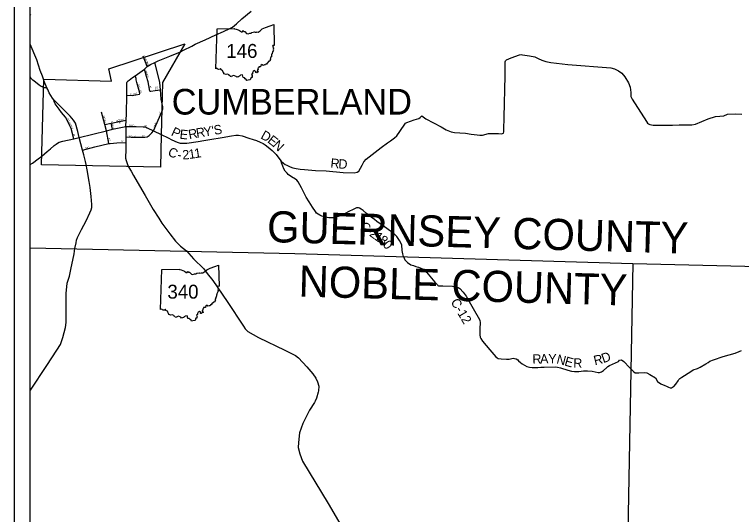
# Model space of a CAD drawing. Extents: x -452339 to 6403467, y -1 to 1814750.
# Drawn here: x -91226 to -67891, y 1614709 to 1630757 of the extents above; entities that cross this region are included whole.
import ezdxf

# ---------------------------------------------------------------- set-up
doc = ezdxf.new("R2010")
doc.units = 0
for name, color, linetype in [('Default', 7, 'Continuous'), ('GM_X_Adjacent_County_Text', 7, 'Continuous'), ('GM_X_County', 7, 'Continuous'), ('GM_X_County_Road', 7, 'Continuous'), ('GM_X_County_ROW', 7, 'Continuous'), ('GM_X_Minor_Lake', 7, 'Continuous'), ('GM_X_Minor_River', 7, 'Continuous'), ('GM_X_Minor_River_Text', 7, 'Continuous'), ('GM_X_Section_Text', 7, 'Continuous'), ('GM_X_Township_Road', 7, 'Continuous')]:
    doc.layers.add(name, color=color, linetype=linetype)

msp = doc.modelspace()

# ---------------------------------------------------------------- linework, layer by layer
at = {"layer": 'Default'}
for p, q in [((-90726, 1597935), (-90726, 1655312)), ((-84767, 1629012), (-84726, 1630303)), ((-86540, 1621284), (-86498, 1622575))]:
    msp.add_line(p, q, dxfattribs=at)
msp.add_lwpolyline([(-91226, 1655812), (-32848, 1655812), (-32848, 1597435), (-91226, 1597435)], close=True, dxfattribs=at)
for points in [[(-84726, 1630303), (-84154, 1630311), (-84162, 1630295), (-84109, 1630292), (-84051, 1630265), (-84003, 1630247), (-83943, 1630206), (-83908, 1630207), (-83893, 1630241), (-83866, 1630214), (-83833, 1630210), (-83777, 1630148), (-83731, 1630135), (-83676, 1630156), (-83635, 1630159), (-83605, 1630180), (-83526, 1630198), (-83504, 1630187), (-83463, 1630190), (-83441, 1630198), (-83405, 1630190), (-83342, 1630238), (-83276, 1630293), (-83175, 1630345), (-83024, 1630394), (-82904, 1630439), (-82887, 1629768)], [(-82887, 1629768), (-82905, 1629759), (-82932, 1629764), (-82950, 1629745), (-82928, 1629714), (-82917, 1629680), (-82927, 1629644), (-82917, 1629614), (-82923, 1629589), (-82941, 1629563), (-82947, 1629540), (-82961, 1629514), (-82960, 1629500), (-82974, 1629489), (-82972, 1629447), (-82979, 1629424), (-82976, 1629404), (-82999, 1629399), (-82994, 1629382), (-83008, 1629369), (-83005, 1629347), (-83022, 1629333), (-83006, 1629305), (-83018, 1629296), (-83029, 1629262), (-83058, 1629255), (-83116, 1629193), (-83137, 1629169), (-83160, 1629163), (-83173, 1629139), (-83201, 1629139), (-83244, 1629122), (-83272, 1629151), (-83320, 1629116), (-83326, 1629076), (-83387, 1629077), (-83385, 1629057), (-83399, 1629051), (-83411, 1629031), (-83404, 1628994), (-83433, 1628985), (-83430, 1628964), (-83411, 1628951), (-83403, 1628911), (-83433, 1628919), (-83458, 1628885), (-83484, 1628893), (-83476, 1628922), (-83520, 1628957), (-83561, 1628929), (-83582, 1628885), (-83583, 1628855), (-83614, 1628837), (-83594, 1628795), (-83597, 1628766), (-83597, 1628738), (-83635, 1628739), (-83659, 1628665)], [(-82665, 1626046), (-82595, 1625989), (-82540, 1625945), (-82481, 1625918), (-82373, 1625870), (-82290, 1625841), (-82190, 1625816), (-82061, 1625797), (-81920, 1625779), (-81565, 1625752), (-81221, 1625739), (-80679, 1625687), (-80322, 1625678), (-80224, 1625693), (-80172, 1625730), (-80072, 1625919), (-80010, 1626029), (-79937, 1626112), (-79742, 1626263), (-79452, 1626484), (-79258, 1626638), (-79154, 1626706), (-79027, 1626797), (-78956, 1626860), (-78855, 1626997), (-78680, 1627269), (-78632, 1627292), (-78393, 1627377), (-78253, 1627424), (-78204, 1627453), (-78156, 1627504), (-78018, 1627410), (-77533, 1627149), (-77370, 1627060), (-77205, 1626991), (-77104, 1626969), (-76934, 1626958), (-76754, 1626949), (-76573, 1626919), (-76372, 1626891), (-76293, 1626880), (-76203, 1626882), (-76016, 1626933), (-75924, 1626937), (-75690, 1626933), (-75604, 1626929), (-75566, 1626939), (-75534, 1626954), (-75523, 1626996), (-75516, 1627060), (-75508, 1627467), (-75480, 1628789), (-75473, 1629177), (-75471, 1629241), (-75463, 1629272), (-75432, 1629302), (-75285, 1629365), (-75011, 1629462), (-74967, 1629471), (-74919, 1629468), (-74690, 1629436), (-74526, 1629395), (-74415, 1629347), (-74300, 1629293), (-74167, 1629248), (-74006, 1629212), (-73469, 1629156), (-72086, 1629042), (-71971, 1629016), (-71834, 1628948), (-71733, 1628872), (-71632, 1628752), (-71519, 1628560), (-71468, 1628421), (-71447, 1628253), (-71443, 1628129), (-71397, 1628040), (-70938, 1627322), (-70903, 1627268), (-70873, 1627251), (-70830, 1627231), (-70724, 1627209), (-70358, 1627202), (-70102, 1627208), (-69894, 1627213), (-69486, 1627218), (-69371, 1627243), (-68960, 1627414), (-68726, 1627489), (-68582, 1627497), (-68462, 1627510), (-68335, 1627558), (-68067, 1627567), (-67879, 1627558)], [(-83659, 1628665), (-83725, 1628651), (-83771, 1628643), (-83788, 1628676), (-83821, 1628694), (-83843, 1628728), (-83890, 1628732), (-83902, 1628779), (-83907, 1628817), (-83972, 1628808), (-83990, 1628784), (-84013, 1628778), (-84026, 1628755), (-84058, 1628753), (-84092, 1628742), (-84114, 1628765), (-84169, 1628788), (-84194, 1628800), (-84246, 1628781), (-84257, 1628759), (-84298, 1628769), (-84308, 1628793), (-84333, 1628801), (-84339, 1628826), (-84392, 1628840), (-84433, 1628835), (-84506, 1628855), (-84510, 1628889), (-84535, 1628930), (-84547, 1628959), (-84593, 1628981), (-84602, 1629015), (-84617, 1629014), (-84630, 1629000), (-84681, 1628994), (-84701, 1629007), (-84730, 1629031), (-84767, 1629012)], [(-86518, 1626906), (-86298, 1626795), (-86180, 1626740), (-86005, 1626661), (-85968, 1626645), (-85909, 1626628), (-85855, 1626623), (-85782, 1626623), (-85690, 1626633), (-85329, 1626685), (-85151, 1626716), (-84955, 1626747), (-84558, 1626811), (-84264, 1626865), (-84120, 1626881), (-84039, 1626881), (-83920, 1626858), (-83706, 1626790), (-83570, 1626747), (-83454, 1626710), (-83340, 1626663), (-83247, 1626620), (-83179, 1626571), (-83083, 1626498), (-82958, 1626394), (-82830, 1626260), (-82738, 1626147), (-82665, 1626046)], [(-78742, 1622988), (-78761, 1623078), (-78784, 1623179), (-78798, 1623360), (-78868, 1623504), (-78954, 1623630), (-79048, 1623725), (-79120, 1623783), (-79230, 1623857), (-79392, 1623970), (-79594, 1624116), (-79671, 1624181), (-79781, 1624255), (-79929, 1624372), (-80038, 1624465), (-80099, 1624511), (-80150, 1624542), (-80188, 1624557), (-80217, 1624557), (-80249, 1624549), (-80309, 1624525), (-80377, 1624490), (-80473, 1624442), (-80637, 1624360), (-80802, 1624285), (-80907, 1624247), (-80969, 1624231), (-81040, 1624226), (-81137, 1624231), (-81239, 1624253), (-81358, 1624286), (-81430, 1624313), (-81484, 1624347), (-81528, 1624385), (-81569, 1624439), (-81666, 1624577), (-81768, 1624741), (-81862, 1624896), (-82016, 1625191), (-82122, 1625382), (-82166, 1625436), (-82208, 1625472), (-82330, 1625546), (-82438, 1625627), (-82479, 1625665), (-82535, 1625734), (-82581, 1625809), (-82615, 1625893), (-82655, 1625992), (-82665, 1626046)], [(-78742, 1622988), (-78696, 1622886), (-78613, 1622802), (-78507, 1622726), (-78418, 1622697), (-78343, 1622669), (-78263, 1622651), (-78150, 1622606), (-78089, 1622560), (-78006, 1622483), (-77733, 1622165), (-77653, 1622077), (-77639, 1622064), (-77613, 1622051), (-77587, 1622052), (-77473, 1622046), (-77172, 1622035), (-77042, 1622015), (-76984, 1621994), (-76933, 1621959), (-76827, 1621849), (-76733, 1621716), (-76636, 1621548), (-76500, 1621320), (-76302, 1620971), (-76285, 1620931), (-76282, 1620871), (-76291, 1620667), (-76293, 1620538), (-76290, 1620470), (-76278, 1620400), (-76256, 1620353), (-76206, 1620276), (-75969, 1619995), (-75771, 1619766), (-75737, 1619735), (-75697, 1619718), (-75606, 1619709), (-75436, 1619690), (-75352, 1619696), (-75221, 1619724), (-75173, 1619717), (-75120, 1619704), (-75074, 1619677), (-75043, 1619645), (-74986, 1619584), (-74932, 1619545), (-74778, 1619460), (-74696, 1619435), (-74610, 1619425), (-74432, 1619430), (-74332, 1619440), (-74228, 1619441), (-73864, 1619450), (-73798, 1619439), (-73703, 1619411), (-73468, 1619337), (-73346, 1619307), (-73255, 1619294), (-73111, 1619293), (-72958, 1619316), (-72888, 1619321), (-72830, 1619324), (-72682, 1619307), (-72493, 1619268), (-72445, 1619267), (-72381, 1619284), (-72318, 1619335), (-72216, 1619425), (-72176, 1619462), (-72125, 1619491), (-71841, 1619618), (-71839, 1619620)], [(-86498, 1622575), (-85926, 1622583), (-85935, 1622567), (-85881, 1622564), (-85823, 1622537), (-85775, 1622519), (-85716, 1622478), (-85680, 1622479), (-85665, 1622512), (-85638, 1622486), (-85605, 1622482), (-85550, 1622420), (-85503, 1622407), (-85448, 1622428), (-85407, 1622431), (-85377, 1622452), (-85299, 1622470), (-85276, 1622459), (-85235, 1622462), (-85214, 1622469), (-85177, 1622462), (-85114, 1622509), (-85048, 1622565), (-84947, 1622617), (-84796, 1622666), (-84677, 1622711), (-84659, 1622040)], [(-84659, 1622040), (-84677, 1622031), (-84704, 1622035), (-84723, 1622017), (-84700, 1621985), (-84689, 1621952), (-84699, 1621916), (-84689, 1621886), (-84696, 1621860), (-84713, 1621835), (-84719, 1621811), (-84734, 1621786), (-84733, 1621772), (-84746, 1621761), (-84744, 1621719), (-84751, 1621696), (-84748, 1621676), (-84771, 1621671), (-84766, 1621654), (-84780, 1621641), (-84777, 1621619), (-84794, 1621605), (-84778, 1621577), (-84791, 1621568), (-84801, 1621534), (-84830, 1621527), (-84888, 1621465), (-84909, 1621441), (-84932, 1621435), (-84945, 1621411), (-84973, 1621411), (-85016, 1621394), (-85044, 1621423), (-85093, 1621388), (-85098, 1621348), (-85160, 1621349), (-85157, 1621329), (-85171, 1621323), (-85183, 1621302), (-85176, 1621266), (-85205, 1621257), (-85202, 1621236), (-85183, 1621223), (-85175, 1621183), (-85206, 1621191), (-85231, 1621157), (-85257, 1621165), (-85248, 1621194), (-85292, 1621228), (-85333, 1621201), (-85355, 1621156), (-85355, 1621126), (-85386, 1621109), (-85366, 1621067), (-85370, 1621038), (-85369, 1621010), (-85407, 1621011), (-85431, 1620937)], [(-85431, 1620937), (-85497, 1620923), (-85544, 1620915), (-85560, 1620948), (-85593, 1620966), (-85615, 1621000), (-85663, 1621004), (-85674, 1621051), (-85679, 1621089), (-85744, 1621079), (-85762, 1621056), (-85785, 1621050), (-85798, 1621027), (-85830, 1621025), (-85864, 1621014), (-85886, 1621037), (-85941, 1621060), (-85966, 1621071), (-86018, 1621053), (-86029, 1621031), (-86070, 1621041), (-86080, 1621065), (-86105, 1621073), (-86111, 1621098), (-86164, 1621112), (-86206, 1621106), (-86278, 1621127), (-86282, 1621161), (-86307, 1621202), (-86319, 1621231), (-86365, 1621252), (-86375, 1621287), (-86389, 1621286), (-86402, 1621272), (-86453, 1621265), (-86474, 1621279), (-86502, 1621303), (-86540, 1621284)], [(-71839, 1619620), (-71809, 1619662), (-71738, 1619671), (-71665, 1619619), (-71482, 1619423), (-71362, 1619296), (-71299, 1619253), (-71187, 1619253), (-71002, 1619271), (-70927, 1619253), (-70832, 1619199), (-70653, 1619092), (-70582, 1618972), (-70483, 1618903), (-70356, 1618845), (-70301, 1618824), (-70235, 1618791), (-70180, 1618774), (-70142, 1618773), (-70101, 1618790), (-70061, 1618815), (-69996, 1618896), (-69926, 1618995), (-69897, 1619038), (-69871, 1619070), (-69808, 1619116), (-69519, 1619303), (-69442, 1619349), (-69299, 1619395), (-69218, 1619437), (-69038, 1619544), (-68960, 1619592), (-68905, 1619627), (-68792, 1619673), (-68480, 1619778), (-68093, 1619891), (-67970, 1619938), (-67891, 1619977)]]:
    msp.add_lwpolyline(points, dxfattribs=at)
at = {"layer": 'GM_X_County_Road'}
for points in [[(-85799, 1629613), (-85531, 1629740), (-85432, 1629803), (-85106, 1629950), (-84767, 1630104), (-84515, 1630211), (-84310, 1630308), (-84234, 1630347), (-84102, 1630454), (-83927, 1630614), (-83625, 1630865)], [(-90286, 1628651), (-90328, 1628776), (-90400, 1628958), (-90511, 1629299), (-90726, 1629811)], [(-87583, 1628627), (-87550, 1628655), (-87434, 1628736), (-87357, 1628787), (-87059, 1629002), (-86964, 1629084), (-86865, 1629151), (-86719, 1629220), (-86617, 1629271), (-86239, 1629419), (-85903, 1629564), (-85799, 1629613)], [(-89149, 1626807), (-89149, 1626807), (-89195, 1627002), (-89269, 1627266), (-89331, 1627366), (-89441, 1627497), (-89522, 1627580), (-89673, 1627733), (-89866, 1627919), (-89959, 1628015), (-90004, 1628076), (-90065, 1628158), (-90112, 1628246), (-90161, 1628349), (-90187, 1628406), (-90284, 1628644), (-90286, 1628651)], [(-87650, 1627168), (-87644, 1627371), (-87637, 1627570), (-87624, 1628165), (-87624, 1628528), (-87618, 1628568), (-87611, 1628593), (-87590, 1628621), (-87583, 1628627)], [(-89149, 1626807), (-88273, 1627020), (-88110, 1627067), (-88083, 1627074), (-87970, 1627102), (-87650, 1627168)], [(-87650, 1627168), (-87650, 1626826), (-87653, 1626653), (-87656, 1626514), (-87655, 1626417)], [(-89951, 1626550), (-89891, 1626598), (-89844, 1626633), (-89789, 1626662), (-89676, 1626696), (-89326, 1626765), (-89149, 1626807)], [(-88931, 1625945), (-88951, 1626042), (-89001, 1626254), (-89040, 1626407), (-89093, 1626607), (-89149, 1626807)], [(-90726, 1625945), (-90650, 1625991), (-90465, 1626130), (-90348, 1626213), (-90177, 1626357), (-90068, 1626446), (-89968, 1626537), (-89951, 1626550)], [(-87655, 1626417), (-87654, 1626380), (-87659, 1626205), (-87659, 1626149), (-87638, 1626073), (-87601, 1625943)], [(-89291, 1623251), (-89250, 1623430), (-89232, 1623510), (-89202, 1623595), (-89152, 1623704), (-89071, 1623858), (-88931, 1624131), (-88804, 1624387), (-88766, 1624487), (-88746, 1624559), (-88744, 1624657), (-88763, 1624913), (-88798, 1625205), (-88827, 1625396), (-88896, 1625776), (-88931, 1625945)], [(-87601, 1625943), (-87600, 1625940), (-87554, 1625846), (-87485, 1625726), (-87406, 1625591), (-87214, 1625258), (-87034, 1624951), (-86773, 1624503), (-86593, 1624217), (-86493, 1624065), (-86398, 1623930), (-86238, 1623714), (-86057, 1623487), (-85897, 1623321), (-85704, 1623175)], [(-90726, 1618679), (-90716, 1618695), (-90184, 1619491), (-89869, 1619978), (-89752, 1620167), (-89675, 1620394), (-89590, 1620709), (-89566, 1620869), (-89564, 1621276), (-89564, 1621797), (-89531, 1622133), (-89460, 1622359), (-89417, 1622572), (-89316, 1623075), (-89291, 1623251)], [(-85704, 1623175), (-85477, 1622915), (-85144, 1622595), (-85039, 1622444), (-84856, 1622217), (-84400, 1621540), (-83881, 1620756), (-83818, 1620663), (-83735, 1620581), (-83391, 1620394), (-82549, 1619984), (-82211, 1619815), (-82108, 1619734), (-81840, 1619447), (-81651, 1619222), (-81555, 1619083), (-81502, 1618968), (-81456, 1618829), (-81471, 1618679), (-81475, 1618635), (-81534, 1618437), (-81573, 1618348), (-81594, 1618298), (-81752, 1618054), (-81972, 1617630), (-82077, 1617329), (-82111, 1617019), (-82121, 1616858), (-82072, 1616655), (-81986, 1616416), (-81162, 1615062), (-80416, 1613793)]]:
    msp.add_lwpolyline(points, dxfattribs=at)
at = {"layer": 'GM_X_County_ROW'}
msp.add_lwpolyline([(-90339, 1628432), (-90371, 1628449), (-90438, 1628489), (-90552, 1628581), (-90641, 1628654), (-90692, 1628700), (-90715, 1628738), (-90726, 1628767)], dxfattribs=at)
at = {"layer": 'GM_X_Minor_Lake'}
for points in [[(-86964, 1629084), (-87098, 1629423)], [(-86761, 1627022), (-86500, 1627638), (-86469, 1627734), (-86469, 1627794), (-86517, 1628043), (-86541, 1628345), (-86560, 1628572), (-86604, 1628761), (-86719, 1629220)], [(-86879, 1628292), (-86940, 1628598), (-86985, 1628772), (-87059, 1629002)], [(-87219, 1628200), (-87204, 1628220), (-87205, 1628238), (-87236, 1628347), (-87296, 1628577), (-87319, 1628665), (-87324, 1628707), (-87336, 1628736), (-87357, 1628787)], [(-90187, 1628406), (-90224, 1628400), (-90273, 1628408), (-90309, 1628416), (-90339, 1628432)], [(-86879, 1628292), (-86847, 1628295), (-86711, 1628318), (-86541, 1628345)], [(-87624, 1628165), (-87452, 1628155), (-87219, 1628200)], [(-89377, 1626978), (-89413, 1627102), (-89460, 1627206), (-89525, 1627344), (-89594, 1627465), (-89714, 1627609), (-89793, 1627721), (-89918, 1627893), (-89958, 1627970), (-89959, 1628015)], [(-88273, 1627023), (-88329, 1627230), (-88434, 1627624)], [(-88329, 1627230), (-88123, 1627272), (-87644, 1627371)], [(-88083, 1627074), (-88123, 1627272)], [(-87650, 1627168), (-87472, 1627165), (-87323, 1627162), (-87100, 1627151)], [(-87100, 1627151), (-87087, 1627151), (-87026, 1627148), (-86967, 1627124), (-86761, 1627022)], [(-89326, 1626765), (-89375, 1626971), (-89377, 1626978)], [(-88202, 1626615), (-88273, 1627020), (-88273, 1627023)], [(-87192, 1626817), (-87184, 1626817), (-87038, 1626816), (-86971, 1626827), (-86906, 1626869), (-86815, 1626960), (-86761, 1627022)], [(-86761, 1627022), (-86518, 1626906)], [(-88157, 1626619), (-87946, 1626643), (-87653, 1626653)], [(-87650, 1626826), (-87483, 1626823), (-87192, 1626817)], [(-89040, 1626407), (-88653, 1626511), (-88202, 1626615), (-88189, 1626616), (-88157, 1626619)]]:
    msp.add_lwpolyline(points, dxfattribs=at)
at = {"layer": 'GM_X_Minor_River_Text'}
for p, q in [((-88198, 1629014), (-85757, 1629819)), ((-85757, 1629819), (-86474, 1628575)), ((-88111, 1628619), (-88198, 1629014)), ((-90357, 1625935), (-90280, 1628679)), ((-90280, 1628679), (-88111, 1628619)), ((-86474, 1628575), (-86518, 1626893)), ((-86518, 1626893), (-86545, 1625859)), ((-86545, 1625859), (-90357, 1625935))]:
    msp.add_line(p, q, dxfattribs=at)
at = {"layer": 'GM_X_Section_Text'}
for p, q in [((-90726, 1623273), (-82223, 1623081)), ((-82223, 1623081), (-71381, 1622766)), ((-71381, 1622766), (-71618, 1609458)), ((-71381, 1622766), (-66133, 1622641))]:
    msp.add_line(p, q, dxfattribs=at)
at = {"layer": 'GM_X_Township_Road'}
msp.add_arc((-90794, 1630828), 119, 305.1621, 323.2771, dxfattribs=at)

# ---------------------------------------------------------------- texts
at = {"layer": 'Default'}
for s, p in [('146', (-84428, 1629365)), ('340', (-86319, 1621637))]:
    msp.add_text(s, height=447.7, dxfattribs=at).set_placement(p)
at = {"layer": 'GM_X_Adjacent_County_Text'}
for s, height, rotation, p in [('CUMBERLAND', 823.7, 0, (-86180, 1627546)), ('GUERNSEY COUNTY', 1000, 358.4232, (-83130, 1623454)), ('NOBLE COUNTY', 1000, 358.4232, (-82115, 1621705))]:
    msp.add_text(s, height=height, rotation=rotation, dxfattribs=at).set_placement(p)
at = {"layer": 'GM_X_County'}
for s, rotation, p in [('P', 334.8716, (-86224, 1626888)), ('R', 9.2551, (-85376, 1626800)), ('Y', 9.2545, (-85133, 1626840)), ("'", 9.2581, (-84872, 1626882)), ('S', 9.253, (-84807, 1626893)), ('E', 353.6707, (-85938, 1626773)), ('R', 11.1712, (-85615, 1626753)), ('D', 330.927, (-83349, 1626793)), ('E', 322.0664, (-83128, 1626671)), ('N', 316.6629, (-82957, 1626538)), ('C', 336.9769, (-86328, 1626239)), ('2', 3.5213, (-85831, 1626103)), ('1', 8.7072, (-85617, 1626118)), ('1', 8.7566, (-85434, 1626146)), ('-', 353.4185, (-86011, 1626119)), ('R', 354.1745, (-81095, 1625845)), ('D', 356.2646, (-80838, 1625819)), ('C', 322.2387, (-80161, 1623899)), ('2', 324.3596, (-79856, 1623669)), ('-', 324.3443, (-79957, 1623741)), ('1', 324.3438, (-79706, 1623562)), ('8', 323.841, (-79557, 1623454)), ('0', 309.7026, (-79422, 1623359)), ('C-12', 300.7441, (-77237, 1621535)), ('D', 19.1785, (-72327, 1619565)), ('R', 1.374, (-74599, 1619546)), ('A', 1.3698, (-74353, 1619552)), ('Y', 0.2732, (-74091, 1619558)), ('N', 345.6881, (-73847, 1619562)), ('E', 343.7773, (-73593, 1619497)), ('R', 359.2429, (-73291, 1619421)), ('R', 13.5478, (-72597, 1619499))]:
    msp.add_text(s, height=300, rotation=rotation, dxfattribs=at).set_placement(p)
at = {"layer": 'GM_X_Minor_River'}
for s, rotation, p in [('SINGER', 293.4993, (-87091, 1629426)), ('RD', 293.9614, (-86999, 1629210)), ('MAPLE', 287.2778, (-87030, 1628945)), ('ELM', 285.9444, (-87271, 1628519)), ('ST', 288.4262, (-87214, 1628316)), ('ST', 284.9242, (-86902, 1628461)), ('1ST', 9.8702, (-86729, 1628384)), ('ST', 7.12, (-86709, 1628330)), ('1', 354.7773, (-87516, 1628173)), ('S', 357.0818, (-87483, 1628170)), ('T', 11.9171, (-87434, 1628169)), ('ST', 10.6213, (-87374, 1628182)), ('ST', 66.8023, (-86553, 1627538)), ('CEMETERY', 295.8879, (-89551, 1627416)), ('BROAD', 285.4621, (-88393, 1627515)), ('NORTH', 12.0102, (-87959, 1627315)), ('BANK ST', 280.7367, (-88125, 1627339)), ('ST', 11.3113, (-87872, 1627249)), ('MAIN', 358.4498, (-87535, 1627178)), ('S', 352.3259, (-87064, 1627161)), ('T', 346.8784, (-87030, 1627156)), ('CARL', 68.1986, (-86725, 1627120)), ('ST', 284.9242, (-89353, 1626921)), ('W', 357.1242, (-87561, 1626835)), ('A', 358.3602, (-87503, 1626832)), ('T', 359.7134, (-87457, 1626831)), ('E', 359.9956, (-87422, 1626831)), ('R', 359.9941, (-87387, 1626831)), ('ST', 280.6135, (-88217, 1626789)), ('ST', 3.5738, (-87813, 1626659)), ('ST', 0, (-87139, 1626826)), ('MILL', 13.6288, (-88950, 1626443))]:
    msp.add_text(s, height=50, rotation=rotation, dxfattribs=at).set_placement(p)

doc.saveas('drawing.dxf')
